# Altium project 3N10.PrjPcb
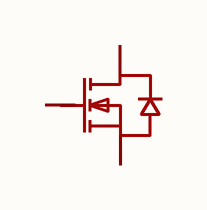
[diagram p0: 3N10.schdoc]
1 sheet, 1 parts. Net scope: global (net labels, ports and power ports of the same name join across sheets).

## Sheet 3N10.schdoc
size 127 x 101 mm

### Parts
Q?  3n10-ms  [SOT-23-3_L2.9-W1.8-P1.90-LS2.4-BR]  (value not drawn)

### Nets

Not connected (* = marked no-connect by the designer): Q? 1(G) 2(S) 3(D)

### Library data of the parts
Q? = 3n10-ms: 数量:1个N沟道;漏源电压(Vdss):100V;连续漏极电流(Id):3A;导通电阻(RDS(on)):90mΩ@10V；120mΩ@4.5V;耗散功率(Pd):1W;阈值电压(Vgs(th)):1.5V;; Manufacturer: MSKSEMI(美森科); Symbol: 3N10; AddInBom: yes; ModelId: 64130a43b5274a59b3370e916a19aa1d; ModelTransform: 94.488,114.173,0,0,0,0,-0.001,0.003,0; Number: 1个N沟道; Drain to Source Voltage: 100V; Current - Continuous Drain(Id): 3A; Pd - Power Dissipation: 1W; Gate Threshold Voltage (Vgs(th)): 1.5V; Gate Charge(Qg): 18nC@10V; Input Capacitance(Ciss): 765pF; Reverse Transfer Capacitance (Crss@Vds): 33pF; Type: N沟道; Output Capacitance(Coss): 38pF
